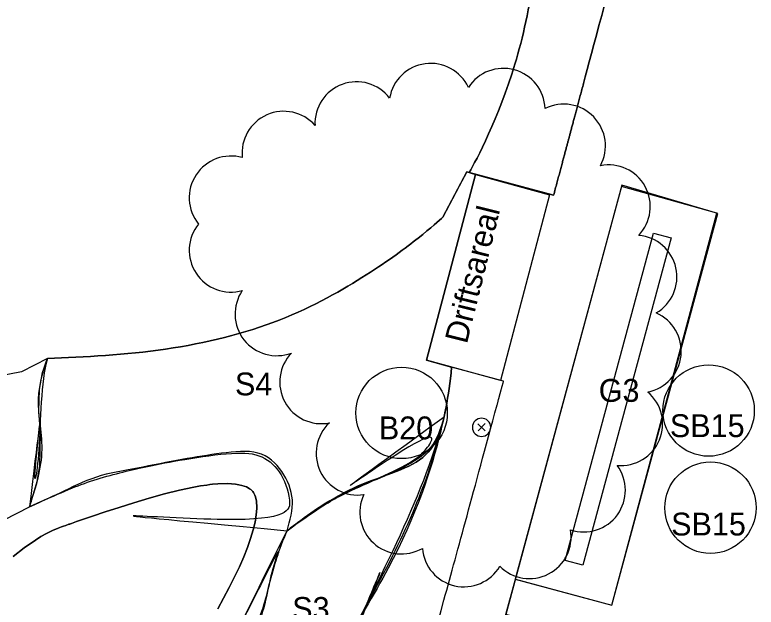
# Model space of a CAD drawing. Extents: x 0 to 512122, y 0 to 6212554.
# Drawn here: x 511701.46 to 511742.02, y 6211649.39 to 6211681.8 of the extents above; entities that cross this region are included whole.
import ezdxf

# ---------------------------------------------------------------- set-up
doc = ezdxf.new("R2010")
doc.units = 0
for name, color, linetype in [('_lights', 7, 'Continuous'), ('_S1_rabarber', 7, 'Continuous'), ('_S2_skovjorbær', 7, 'Continuous'), ('_S3_Mynte', 7, 'Continuous'), ('_S4_Løvstikke', 7, 'Continuous'), ('_S5_spansk kørvel', 7, 'Continuous'), ('Bassin - bottom', 7, 'Continuous'), ('Clouds', 7, 'Continuous'), ('L40 jord udlagt muld og grøft', 7, 'Continuous'), ('Pumpstation', 7, 'Continuous'), ('TV_U_AFM_Symbl_Gul', 7, 'Continuous'), ('TV_U_LYS_Mastenummer', 7, 'Continuous'), ('TV_U_LYS_Nyx330-Trafiksti-x2', 7, 'Continuous')]:
    doc.layers.add(name, color=color, linetype=linetype)

msp = doc.modelspace()

# ---------------------------------------------------------------- linework, layer by layer
at = {"layer": '_lights'}
for p, q in [((511726.795, 6211659.428), (511727.189, 6211659.034)), ((511727.193, 6211659.432), (511726.799, 6211659.038))]:
    msp.add_line(p, q, dxfattribs=at)
for start, end in [(315.5636, 315), (315, 315.5636)]:
    msp.add_arc((511726.992, 6211659.231), 0.5, start, end, dxfattribs=at)
at = {"layer": '_S1_rabarber'}
for p, q in [((511730.933, 6211671.928), (511726.316, 6211673.166)), ((511726.316, 6211673.166), (511730.933, 6211671.928)), ((511728.194, 6211661.759), (511725.352, 6211662.529)), ((511728.194, 6211661.759), (511725.352, 6211662.529))]:
    msp.add_line(p, q, dxfattribs=at)
for points, degree in [([(511734.603, 6211757.422), (511735.331, 6211754.157), (511736.949, 6211746.893), (511739.141, 6211736.177), (511740.137, 6211725.286), (511740.362, 6211712.579), (511738.054, 6211698.643), (511734.81, 6211686.446), (511733.067, 6211679.907), (511732.568, 6211678.04)], 3), ([(511732.568, 6211678.04), (511733.067, 6211679.907), (511734.81, 6211686.446), (511738.054, 6211698.643), (511740.362, 6211712.579), (511740.137, 6211725.286), (511739.141, 6211736.177), (511736.949, 6211746.893), (511735.331, 6211754.157), (511734.603, 6211757.422)], 3), ([(511726.316, 6211673.166), (511726.701, 6211673.84), (511729.166, 6211678.46), (511730.77, 6211689.196), (511731.359, 6211707.945), (511730.809, 6211726.91), (511728.592, 6211740.772), (511727.934, 6211745.488), (511727.864, 6211745.992)], 3), ([(511727.864, 6211745.992), (511727.934, 6211745.488), (511728.592, 6211740.772), (511730.809, 6211726.91), (511731.359, 6211707.945), (511730.77, 6211689.196), (511729.166, 6211678.46), (511726.701, 6211673.84), (511726.316, 6211673.166)], 3), ([(511732.568, 6211678.04), (511732.024, 6211676.003), (511731.48, 6211673.965), (511730.933, 6211671.928)], 2), ([(511730.933, 6211671.928), (511731.48, 6211673.965), (511732.024, 6211676.003), (511732.568, 6211678.04)], 2), ([(511725.352, 6211662.529), (511725.349, 6211662.493), (511725.092, 6211659.458), (511722.57, 6211651.867), (511715.885, 6211642.179), (511715.448, 6211631.484), (511715.258, 6211624.37), (511713.955, 6211621.257), (511713.443, 6211620.033)], 3), ([(511725.352, 6211662.529), (511725.349, 6211662.493), (511725.092, 6211659.458), (511722.57, 6211651.867), (511715.885, 6211642.179), (511715.448, 6211631.484), (511715.258, 6211624.37), (511713.955, 6211621.257), (511713.443, 6211620.033)], 3), ([(511727.845, 6211660.47), (511727.962, 6211660.9), (511728.078, 6211661.33), (511728.194, 6211661.759)], 2), ([(511727.845, 6211660.47), (511727.962, 6211660.9), (511728.078, 6211661.33), (511728.194, 6211661.759)], 2), ([(511723.059, 6211642.917), (511723.333, 6211643.917), (511724.935, 6211649.766), (511726.53, 6211655.617), (511727.845, 6211660.47)], 3), ([(511723.059, 6211642.917), (511723.333, 6211643.917), (511724.935, 6211649.766), (511726.53, 6211655.617), (511727.845, 6211660.47)], 3)]:
    msp.add_open_spline(points, degree=degree, dxfattribs=at)
at = {"layer": '_S2_skovjorbær'}
msp.add_line((511728.026, 6211661.801), (511723.974, 6211662.912), dxfattribs=at)
at = {"layer": '_S3_Mynte'}
for points in [[(511724.952, 6211659.807), (511724.306, 6211657.401), (511722.522, 6211653.033), (511718.71, 6211645.702), (511717.032, 6211641.695), (511716.159, 6211638.46), (511724.952, 6211659.807), (511716.159, 6211638.46)], [(511716.159, 6211638.46), (511716.422, 6211639.547), (511717.026, 6211642.044), (511719.194, 6211646.93), (511722.109, 6211651.909), (511724.172, 6211656.666), (511724.752, 6211659), (511724.952, 6211659.807)], [(511716.355, 6211653.575), (511717.953, 6211654.746), (511719.23, 6211655.515), (511720.941, 6211656.255), (511722.971, 6211657.184), (511724.074, 6211657.967), (511724.952, 6211659.807), (511716.355, 6211653.575), (511724.952, 6211659.807)], [(511724.952, 6211659.807), (511724.737, 6211659.131), (511724.38, 6211658.008), (511722.714, 6211657.001), (511721.065, 6211656.291), (511719.317, 6211655.618), (511717.802, 6211654.675), (511716.881, 6211653.975), (511716.355, 6211653.575)], [(511711.36, 6211643.536), (511711.891, 6211644.398), (511712.422, 6211644.945), (511714.272, 6211647.442), (511715.067, 6211649.303), (511715.306, 6211650.373), (511715.73, 6211652.007), (511716.355, 6211653.575), (511711.36, 6211643.536), (511716.355, 6211653.575)], [(511716.355, 6211653.575), (511716.131, 6211653.058), (511715.683, 6211652.023), (511715.335, 6211650.569), (511715.041, 6211648.99), (511714.161, 6211647.086), (511713.013, 6211645.467), (511711.799, 6211644.365), (511711.52, 6211643.837), (511711.36, 6211643.536)]]:
    msp.add_open_spline(points, degree=3, dxfattribs=at)
at = {"layer": '_S4_Løvstikke'}
for p, q in [((511726.189, 6211673.212), (511725.774, 6211672.425)), ((511726.665, 6211673.058), (511726.189, 6211673.212)), ((511723.975, 6211662.904), (511726.665, 6211673.058)), ((511725.774, 6211672.425), (511724.878, 6211670.725)), ((511725.352, 6211662.529), (511723.975, 6211662.904))]:
    msp.add_line(p, q, dxfattribs=at)
msp.add_lwpolyline([(511724.878, 6211670.725), (511726.189, 6211673.212), (511726.665, 6211673.058), (511723.975, 6211662.904), (511725.352, 6211662.529)], dxfattribs=at)
for points in [[(511724.878, 6211670.725), (511724.695, 6211670.562), (511723.734, 6211669.705), (511721.041, 6211667.703), (511716.193, 6211664.9), (511709.75, 6211663.295), (511705.269, 6211663.083), (511703.238, 6211662.987)], [(511703.238, 6211662.987), (511705.269, 6211663.083), (511709.75, 6211663.295), (511716.193, 6211664.9), (511721.041, 6211667.703), (511723.734, 6211669.705), (511724.695, 6211670.562), (511724.878, 6211670.725)], [(511703.238, 6211662.987), (511702.871, 6211661.761), (511702.871, 6211657.32), (511702.255, 6211654.885), (511703.238, 6211662.987), (511702.255, 6211654.885)], [(511702.255, 6211654.885), (511702.522, 6211655.689), (511703.26, 6211657.913), (511702.46, 6211660.767), (511703.096, 6211662.581), (511703.238, 6211662.987)], [(511716.355, 6211653.575), (511717.245, 6211654.25), (511719.883, 6211656.251), (511724.415, 6211657.176), (511725.1, 6211660.521), (511725.269, 6211661.631), (511725.352, 6211662.529)], [(511725.352, 6211662.529), (511725.269, 6211661.631), (511725.1, 6211660.521), (511724.415, 6211657.176), (511719.883, 6211656.251), (511717.245, 6211654.25), (511716.355, 6211653.575)], [(511716.355, 6211653.575), (511716.512, 6211654.138), (511716.831, 6211655.287), (511716.16, 6211656.875), (511714.905, 6211658.065), (511712.737, 6211657.821), (511710.687, 6211657.506), (511708.096, 6211656.969), (511705.89, 6211656.619), (511703.883, 6211655.593), (511702.797, 6211655.121), (511702.255, 6211654.885)], [(511702.255, 6211654.885), (511703.876, 6211655.61), (511705.495, 6211656.342), (511708.581, 6211657.079), (511710.231, 6211657.401), (511713.257, 6211657.872), (511714.905, 6211657.821), (511715.989, 6211656.915), (511716.633, 6211655.259), (511716.355, 6211653.575), (511702.255, 6211654.885), (511716.355, 6211653.575)]]:
    msp.add_open_spline(points, degree=3, dxfattribs=at)
at = {"layer": '_S5_spansk kørvel'}
msp.add_lwpolyline([(511703.238, 6211662.987), (511701.822, 6211662.264), (511689.868, 6211659.949), (511685.155, 6211659.338), (511685.411, 6211657.783), (511685.244, 6211656.619), (511684.849, 6211655.83), (511691.642, 6211651.943), (511691.91, 6211651.609), (511692.695, 6211651.377), (511693.07, 6211651.448), (511694.206, 6211651.71), (511695.721, 6211651.856), (511697.411, 6211652.409), (511702.255, 6211654.885), (511702.655, 6211656.155), (511702.821, 6211657.124), (511702.863, 6211658.926), (511702.771, 6211660.108), (511702.807, 6211661.293), (511702.978, 6211662.238)], close=True, dxfattribs=at)
msp.add_lwpolyline([(511703.238, 6211662.987), (511701.822, 6211662.264), (511689.868, 6211659.949), (511685.155, 6211659.338), (511685.411, 6211657.783), (511685.244, 6211656.619), (511684.849, 6211655.83), (511691.642, 6211651.943), (511691.91, 6211651.609), (511692.695, 6211651.377), (511693.07, 6211651.448), (511694.206, 6211651.71), (511695.721, 6211651.856), (511697.411, 6211652.409), (511702.255, 6211654.885), (511702.655, 6211656.155), (511702.821, 6211657.124), (511702.863, 6211658.926), (511702.771, 6211660.108), (511702.807, 6211661.293), (511702.978, 6211662.238)], close=True, dxfattribs=at)
at = {"layer": 'Bassin - bottom'}
msp.add_lwpolyline([(511701.358, 6211652.169), (511701.971, 6211652.639), (511702.58, 6211653.063), (511702.887, 6211653.253), (511703.196, 6211653.426), (511703.511, 6211653.582), (511703.832, 6211653.718), (511703.915, 6211653.75), (511704.007, 6211653.783), (511704.116, 6211653.822), (511704.249, 6211653.869), (511704.412, 6211653.925), (511704.458, 6211653.941), (511704.506, 6211653.958), (511704.839, 6211654.074), (511705.099, 6211654.164), (511705.7, 6211654.371), (511706.394, 6211654.604), (511707.157, 6211654.853), (511707.969, 6211655.106), (511708.808, 6211655.354), (511709.65, 6211655.585), (511710.472, 6211655.789), (511711.25, 6211655.956), (511711.614, 6211656.021), (511711.956, 6211656.074), (511712.119, 6211656.095), (511712.275, 6211656.112), (511712.571, 6211656.138), (511713.095, 6211656.151), (511713.528, 6211656.121), (511713.71, 6211656.092), (511713.869, 6211656.056), (511714.007, 6211656.015), (511714.123, 6211655.97), (511714.221, 6211655.922), (511714.302, 6211655.873), (511714.369, 6211655.823), (511714.426, 6211655.771), (511714.474, 6211655.717), (511714.517, 6211655.659), (511714.555, 6211655.593), (511714.59, 6211655.517), (511714.621, 6211655.43), (511714.648, 6211655.33), (511714.669, 6211655.217), (511714.684, 6211655.089), (511714.692, 6211654.947), (511714.691, 6211654.792), (511714.663, 6211654.444), (511714.598, 6211654.051), (511714.495, 6211653.619), (511714.356, 6211653.153), (511714.182, 6211652.659), (511713.976, 6211652.139), (511713.74, 6211651.599), (511713.191, 6211650.47), (511712.557, 6211649.297)], dxfattribs=at)
at = {"layer": 'Clouds'}
for centre, radius, start, end in [((511724.211, 6211676.858), 2.281, 25.2077, 170.2077), ((511728.186, 6211676.588), 2.28, 2.0157, 147.0157), ((511720.158, 6211675.852), 2.281, 37.6761, 182.6761), ((511731.487, 6211674.628), 2.282, 331.608, 116.608), ((511716.167, 6211674.238), 2.281, 41.3523, 186.3523), ((511713.279, 6211671.792), 2.28, 74.1952, 219.1952), ((511733.941, 6211671.307), 2.281, 316.3178, 101.3178), ((511713.28, 6211668.911), 2.281, 140.8408, 285.8408), ((511735.4, 6211667.459), 2.281, 300.1916, 85.1916), ((511715.786, 6211665.43), 2.281, 145.6596, 290.6596), ((511735.635, 6211663.397), 2.281, 281.4375, 66.4375), ((511718.231, 6211661.711), 2.281, 135.9748, 280.9748), ((511734.617, 6211659.418), 2.281, 264.8625, 49.8625), ((511720.223, 6211657.807), 2.281, 133.096, 278.096), ((511732.58, 6211655.788), 2.281, 251.5454, 36.5454), ((511722.612, 6211654.585), 2.281, 154.9974, 299.9974), ((511729.611, 6211653.238), 2.28, 224.7551, 9.7551), ((511726.026, 6211652.789), 2.281, 184.528, 329.528)]:
    msp.add_arc(centre, radius, start, end, dxfattribs=at)
at = {"layer": 'L40 jord udlagt muld og grøft'}
msp.add_lwpolyline([(511719.958, 6211597.433), (511721.235, 6211601.868), (511723.218, 6211609.192), (511730.526, 6211636.221), (511733.595, 6211647.574), (511728.319, 6211648.988), (511728.841, 6211650.918), (511734.117, 6211649.504), (511739.91, 6211670.932), (511734.664, 6211672.473), (511728.315, 6211648.989), (511717.418, 6211608.688), (511715.74, 6211602.51), (511714.965, 6211599.808), (511714.305, 6211597.689)], dxfattribs=at)
for points in [[(511734.645, 6211672.4), (511728.837, 6211650.919), (511734.117, 6211649.504), (511739.86, 6211670.938)], [(511736.405, 6211669.852), (511737.371, 6211669.591), (511732.531, 6211651.689), (511731.565, 6211651.948)]]:
    msp.add_lwpolyline(points, close=True, dxfattribs=at)
at = {"layer": 'Pumpstation'}
msp.add_lwpolyline([(511726.665, 6211673.058), (511730.717, 6211671.957), (511728.027, 6211661.799), (511723.975, 6211662.904), (511726.667, 6211673.058)], dxfattribs=at)
at = {"layer": 'TV_U_LYS_Mastenummer'}
for centre in [(511739.414, 6211660.148), (511739.414, 6211660.148), (511722.618, 6211660.018), (511739.515, 6211654.834), (511739.515, 6211654.834)]:
    msp.add_circle(centre, 2.5, dxfattribs=at)
at = {"layer": 'TV_U_LYS_Nyx330-Trafiksti-x2'}
msp.add_lwpolyline([(511712.557, 6211649.297), (511713.191, 6211650.47), (511713.74, 6211651.599), (511713.976, 6211652.139), (511714.182, 6211652.659), (511714.356, 6211653.153), (511714.495, 6211653.619), (511714.598, 6211654.051), (511714.663, 6211654.444), (511714.691, 6211654.792), (511714.692, 6211654.947), (511714.684, 6211655.089), (511714.669, 6211655.217), (511714.648, 6211655.33), (511714.621, 6211655.43), (511714.59, 6211655.517), (511714.555, 6211655.593), (511714.517, 6211655.659), (511714.474, 6211655.717), (511714.426, 6211655.771), (511714.369, 6211655.823), (511714.302, 6211655.873), (511714.221, 6211655.922), (511714.123, 6211655.97), (511714.007, 6211656.015), (511713.869, 6211656.056), (511713.71, 6211656.092), (511713.528, 6211656.121), (511713.095, 6211656.151), (511712.571, 6211656.138), (511712.275, 6211656.112), (511712.119, 6211656.095), (511711.956, 6211656.074), (511711.614, 6211656.021), (511711.25, 6211655.956), (511710.472, 6211655.789), (511709.65, 6211655.585), (511708.808, 6211655.354), (511707.969, 6211655.106), (511707.157, 6211654.853), (511706.394, 6211654.604), (511705.7, 6211654.371), (511705.099, 6211654.164), (511704.839, 6211654.074), (511704.609, 6211653.994), (511704.506, 6211653.958), (511704.458, 6211653.941), (511704.412, 6211653.925), (511704.249, 6211653.869), (511704.116, 6211653.822), (511704.007, 6211653.783), (511703.915, 6211653.75), (511703.832, 6211653.718), (511703.511, 6211653.582), (511703.196, 6211653.426), (511702.887, 6211653.253), (511702.58, 6211653.063), (511701.971, 6211652.639), (511701.358, 6211652.169)], dxfattribs=at)

# ---------------------------------------------------------------- texts
at = {"layer": 'TV_U_AFM_Symbl_Gul'}
msp.add_text('Driftsareal', height=1.25, rotation=76.1034, dxfattribs=at).set_placement((511726.186, 6211663.752))
for s, p in [('S4', (511713.499, 6211660.979)), ('G3', (511733.402, 6211660.624)), ('B20', (511721.372, 6211658.574)), ('SB15', (511737.295, 6211658.694)), ('SB15', (511737.363, 6211653.313)), ('S3', (511716.632, 6211648.695))]:
    msp.add_text(s, height=1.25, dxfattribs=at).set_placement(p)

doc.saveas('drawing.dxf')
